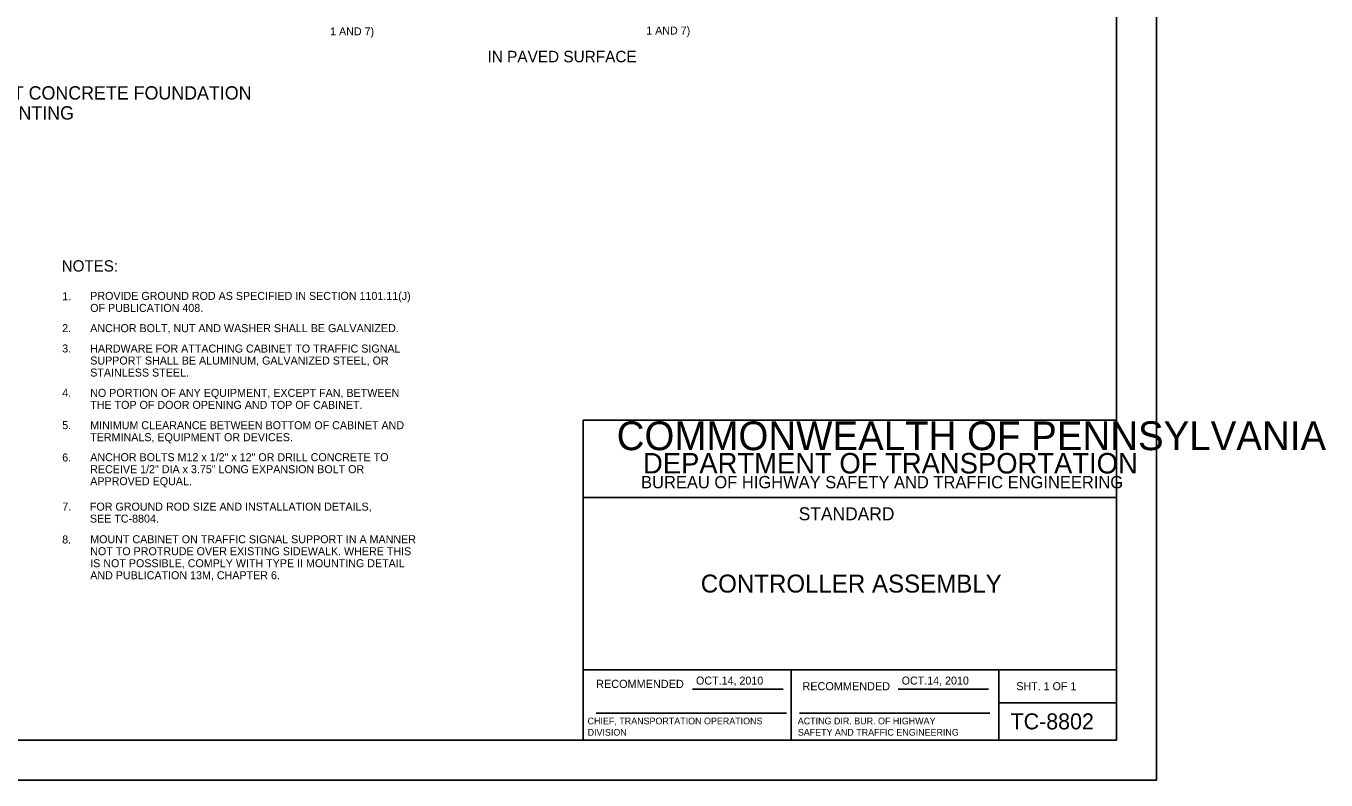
# Model space of a CAD drawing. Extents: x -855 to 49, y 616 to 1210.
# Drawn here: x -438 to 49.4, y 616.2 to 899 of the extents above; entities that cross this region are included whole.
import ezdxf

# ---------------------------------------------------------------- set-up
doc = ezdxf.new("R2010")
doc.units = 0
for name, color, linetype in [('1', 7, 'Continuous'), ('2', 7, 'Continuous'), ('4', 7, 'Continuous'), ('Default', 7, 'Continuous'), ('PLT-BNDY', 7, 'Continuous')]:
    doc.layers.add(name, color=color, linetype=linetype)

msp = doc.modelspace()

# ---------------------------------------------------------------- linework, layer by layer
at = {"layer": '1'}
for p, q in [((-29.14, 631.17), (-29.14, 1195.17)), ((-229.14, 631.17), (-229.14, 751.17)), ((-229.14, 751.17), (-29.14, 751.17)), ((-29.14, 722.17), (-229.14, 722.17)), ((-229.14, 657.55), (-29.14, 657.55)), ((-151.14, 657.55), (-151.14, 631.17)), ((-73.27, 631.17), (-73.27, 657.55)), ((-188.1, 650.2), (-154.18, 650.2)), ((-111.01, 650.2), (-77.09, 650.2)), ((-73.27, 645.17), (-29.14, 645.17)), ((-224.26, 641.21), (-152.93, 641.21)), ((-148.05, 641.21), (-76.59, 641.21)), ((-29.14, 631.17), (-815.14, 631.17)), ((-815.14, 631.17), (-229.14, 631.17))]:
    msp.add_line(p, q, dxfattribs=at)
at = {"layer": 'PLT-BNDY'}
msp.add_lwpolyline([(-855.14, 1210.17), (-14.14, 1210.17), (-14.14, 616.17), (-855.14, 616.17)], close=True, dxfattribs=at)

# ---------------------------------------------------------------- texts
at = {"layer": '1'}
for s, height, p in [('COMMONWEALTH OF PENNSYLVANIA', 10.7828, (-216.55, 739.9)), ('DEPARTMENT OF TRANSPORTATION', 7.6837, (-206.69, 731.15)), ('BUREAU OF HIGHWAY SAFETY AND TRAFFIC ENGINEERING', 4.6253, (-207.42, 725.59)), ('CONTROLLER ASSEMBLY', 6.75, (-185.03, 686.48)), ('RECOMMENDED', 3.0516, (-224.27, 650.7)), ('OCT.14, 2010', 3, (-186.8, 651.97)), ('RECOMMENDED', 3.0516, (-146.92, 649.82)), ('SHT. 1 OF 1', 3, (-66.71, 649.86)), ('TC-8802', 6, (-68.86, 635.17))]:
    msp.add_text(s, height=height, dxfattribs=at).set_placement(p)
msp.add_text('OCT.14, 2010', height=3, rotation=360, dxfattribs=at).set_placement((-109.7, 651.97))
at = {"layer": '2'}
for s, height, p in [('1 AND 7)', 3, (-324.01, 895.49)), ('1 AND 7)', 3, (-205.48, 895.79)), ('IN PAVED SURFACE', 4.3, (-264.98, 885.39)), ('CONTROLLER ASSEMBLY ON CEMENT CONCRETE FOUNDATION', 5, (-564.48, 871.41)), ('TYPE I MOUNTING', 5, (-479.48, 863.91)), ('NOTES:', 4.25, (-424.66, 806.89)), ('PROVIDE GROUND ROD AS SPECIFIED IN SECTION 1101.11(J) ', 3, (-413.96, 796.26)), ('1.', 3, (-424.41, 796.15)), ('OF PUBLICATION 408.', 3, (-413.96, 791.76)), ('2.', 3, (-424.46, 784.16)), ('ANCHOR BOLT, NUT AND WASHER SHALL BE GALVANIZED.', 3, (-413.96, 784.16)), ('3.', 3, (-424.46, 776.54)), ('SUPPORT SHALL BE ALUMINUM, GALVANIZED STEEL, OR', 3, (-413.96, 772.01)), ('HARDWARE FOR ATTACHING CABINET TO TRAFFIC SIGNAL', 3, (-413.96, 776.51)), ('STAINLESS STEEL.', 3, (-413.96, 767.51)), ('4.', 3, (-424.46, 759.91)), ('NO PORTION OF ANY EQUIPMENT, EXCEPT FAN, BETWEEN', 3, (-413.96, 759.89)), ('THE TOP OF DOOR OPENING AND TOP OF CABINET.', 3, (-413.96, 755.39)), ('5.', 3, (-424.46, 747.79)), ('MINIMUM CLEARANCE BETWEEN BOTTOM OF CABINET AND', 3, (-413.96, 747.76)), ('TERMINALS, EQUIPMENT OR DEVICES.', 3, (-413.96, 743.26)), ('6.', 3, (-424.46, 735.66)), ('ANCHOR BOLTS M12 x 1/2" x 12" OR DRILL CONCRETE TO', 3, (-413.96, 735.76)), ('RECEIVE 1/2" DIA x 3.75" LONG EXPANSION BOLT OR', 3, (-413.96, 731.26)), ('APPROVED EQUAL.', 3, (-413.96, 726.76)), ('7.', 3, (-424.42, 717.22)), ('FOR GROUND ROD SIZE AND INSTALLATION DETAILS,', 3, (-414.08, 717.22)), ('SEE TC-8804.', 3, (-414.08, 712.72)), ('8.', 3, (-424.46, 704.88)), ('MOUNT CABINET ON TRAFFIC SIGNAL SUPPORT IN A MANNER', 3, (-413.96, 704.98)), ('NOT TO PROTRUDE OVER EXISTING SIDEWALK. WHERE THIS', 3, (-413.96, 700.48)), ('IS NOT POSSIBLE, COMPLY WITH TYPE II MOUNTING DETAIL', 3, (-413.96, 695.98)), ('AND PUBLICATION 13M, CHAPTER 6.', 3, (-413.96, 691.48))]:
    msp.add_text(s, height=height, dxfattribs=at).set_placement(p)
at = {"layer": '4'}
msp.add_text('STANDARD', height=4.881, rotation=360, dxfattribs=at).set_placement((-148.31, 713.59))
at = {"layer": 'Default'}
for s, p in [('CHIEF, TRANSPORTATION OPERATIONS', (-227.46, 637.06)), ('ACTING DIR. BUR. OF HIGHWAY', (-148.65, 637.06)), ('DIVISION', (-227.46, 632.81)), ('SAFETY AND TRAFFIC ENGINEERING', (-148.65, 632.81))]:
    msp.add_text(s, height=2.5, dxfattribs=at).set_placement(p)

doc.saveas('drawing.dxf')
